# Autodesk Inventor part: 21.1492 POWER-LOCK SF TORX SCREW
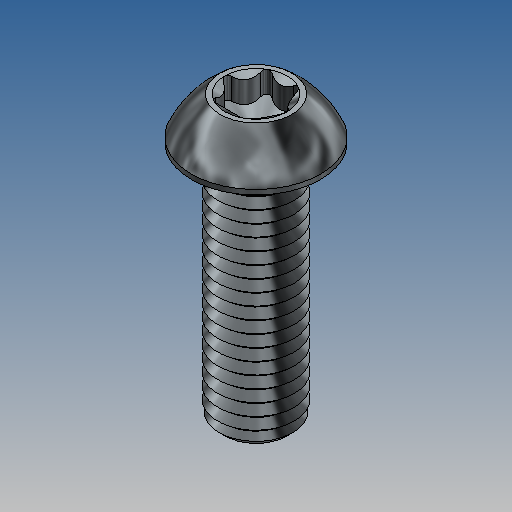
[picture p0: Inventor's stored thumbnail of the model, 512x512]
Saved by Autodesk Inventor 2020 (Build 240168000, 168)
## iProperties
Created: 2009-01
Part Number: 21.1492 POWER-LOCK SF TORX SCREW
Document SubType Name: Modeling
Designer: Administrator
Density: 7.86 g/cm^3
Material: Steel, Mild
Mass: 11.0398 g
Surface Area: 13.2193 cm^2
Volume: 1.40456 cm^3
Appearance: Zinc
Author: Administrator
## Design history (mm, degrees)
feature "Base1"
body "Solid1"
